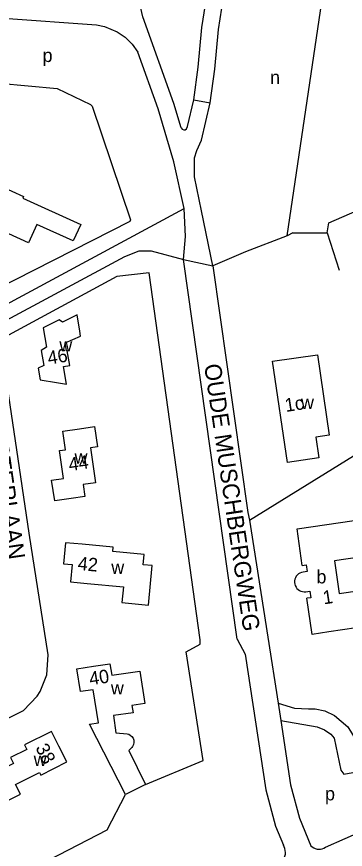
# Model space of a CAD drawing. Extents: x 162427 to 165104, y 384242 to 386287.
# Drawn here: x 164107.7 to 164205.6, y 384987.1 to 385235.6 of the extents above; entities that cross this region are included whole.
import ezdxf

# ---------------------------------------------------------------- set-up
doc = ezdxf.new("R2010")
doc.units = 0
for name, color, linetype in [('BLT_Basislijn', 7, 'Continuous'), ('BLT_Bebouwing', 7, 'Continuous'), ('BLT_Centroide', 7, 'Continuous'), ('BLT_Huisnummer', 7, 'Continuous'), ('BLT_Straatnaam', 7, 'Continuous'), ('BLT_Vlakafsluiter', 7, 'Continuous')]:
    doc.layers.add(name, color=color, linetype=linetype)

msp = doc.modelspace()

# ---------------------------------------------------------------- linework, layer by layer
at = {"layer": 'BLT_Basislijn'}
for p, q in [((164160.47, 385210.78), (164165.39, 385209.89)), ((164100.08, 385147.29), (164157.64, 385178.38)), ((164190.02, 385171.08), (164188.33, 385170.23)), ((164200.2, 385171.13), (164203.77, 385160)), ((164173.43, 385049.82), (164157.35, 385163.13)), ((164177.09, 385085.33), (164231.58, 385119.14)), ((164177.09, 385085.33), (164182.55, 385050.49)), ((164182.55, 385050.49), (164185.59, 385030.74)), ((164199.69, 384987.79), (164222.18, 384997.74))]:
    msp.add_line(p, q, dxfattribs=at)
for points in [[(164160.47, 385210.78), (164161.77, 385220.52), (164162.86, 385232.42), (164166.91, 385258.07), (164172.04, 385290.52), (164175.66, 385314.64)], [(164165.39, 385209.89), (164166.74, 385219.96), (164167.83, 385231.8), (164171.85, 385257.29), (164176.98, 385289.76), (164177.71, 385294.61)], [(164188.33, 385170.23), (164202.97, 385269.71), (164249.26, 385269.42), (164252.4, 385292.86)], [(163719.72, 385227.97), (163758.68, 385247.63), (163770.66, 385252.86), (163778.27, 385255.65), (163784.87, 385257.24), (163794.66, 385258.7), (163805.08, 385259.08), (163818.56, 385258.83), (163833.99, 385257.58), (163913.29, 385250.18), (164037.15, 385240.92), (164075.9, 385237.19), (164131.43, 385233.17)], [(163916.82, 385191.96), (163921.31, 385239.96), (164098.8, 385223.67), (164102.32, 385215.75), (164119.72, 385214.13), (164129.68, 385209.43), (164130.16, 385208.88), (164141.58, 385174.96), (164141.42, 385174.48), (164095.83, 385151.36)], [(164156.7, 385202.45), (164154.56, 385209.7), (164145.31, 385235.52), (164144.24, 385239.86)], [(164131.43, 385233.17), (164133.82, 385232.66), (164137.66, 385231.04), (164140.03, 385229.46), (164142.06, 385227.41), (164143.75, 385225.06)], [(164157.64, 385178.38), (164154.47, 385192.32), (164149.81, 385208.15), (164143.75, 385225.06)], [(164156.7, 385202.45), (164157.02, 385202.02), (164157.54, 385201.88), (164157.92, 385201.86), (164158.32, 385202.17), (164158.63, 385202.88), (164160.47, 385210.78)], [(164160.66, 385187.86), (164160.66, 385193.47), (164161.41, 385195.64), (164162.81, 385198.76), (164165.39, 385209.89)], [(164166.18, 385161.25), (164162.77, 385177.62), (164160.66, 385187.86)], [(164200.2, 385171.13), (164200.68, 385174.05), (164230.63, 385187.13)], [(164157.35, 385163.13), (164158.02, 385169.98), (164157.64, 385178.38)], [(164190.02, 385171.08), (164200.2, 385171.13)], [(164188.33, 385170.23), (164175.9, 385165.47), (164166.18, 385161.25)], [(164101.95, 385143.68), (164139.93, 385164.03), (164144.2, 385165.75), (164147.78, 385165.76), (164157.35, 385163.13)], [(164166.18, 385161.25), (164176.56, 385087.63), (164177.09, 385085.33)], [(164146.05, 385006.5), (164163.21, 385013.65), (164158.19, 385046.13), (164162.37, 385048.39), (164162.37, 385049.63), (164147.21, 385159.13), (164137.48, 385158.1), (164102.85, 385139.32)], [(163874.37, 384930.96), (163895.29, 384941.69), (163907.09, 384947.2), (163917.37, 384950.98), (163935.42, 384955.81), (163969.74, 384962.82), (163983.96, 384967.15), (163993.92, 384971.28), (164109.67, 385028.61), (164113.77, 385032.85), (164114.66, 385034.28), (164116.64, 385039.21), (164117.08, 385045.22), (164111.4, 385081.45), (164102.85, 385139.32)], [(164173.43, 385049.82), (164175.75, 385045.35), (164181.97, 385004.92), (164184.8, 384994.08), (164187.17, 384988.37)], [(164185.59, 385030.74), (164190.51, 385029.27), (164194.66, 385029.06)], [(164185.59, 385030.74), (164186.38, 385025.61)], [(164194.66, 385029.06), (164196.65, 385029.06), (164199.51, 385028.45), (164202.44, 385027.1), (164206.36, 385023.7), (164208.9, 385019.64), (164219.53, 385019.77), (164232.23, 385018.65)], [(164186.38, 385025.61), (164189.32, 385006.44), (164191.93, 384996.48), (164195.36, 384988.2)], [(164186.38, 385025.61), (164197.23, 385023.67), (164199.45, 385022.76), (164201.34, 385021.55), (164202.3, 385020.28), (164204.29, 385010.8), (164205.15, 385009.62), (164216.58, 385011.65)], [(163937.33, 384901.61), (163960, 384913.99), (163988.04, 384927.89), (163995.38, 384923.27), (164065.59, 384957.24), (164134.64, 384992.97), (164140.11, 385003.48)], [(164184.41, 384982.15), (164184.97, 384982.29), (164185.5, 384982.51), (164185.99, 384982.8), (164186.44, 384983.16), (164186.84, 384983.58), (164187.17, 384984.05), (164187.44, 384984.55), (164187.63, 384985.1), (164187.75, 384985.66), (164187.78, 384986.23), (164187.74, 384986.8), (164187.62, 384987.37), (164187.42, 384987.91), (164187.17, 384988.37)], [(164195.36, 384988.2), (164195.76, 384987.86), (164196.21, 384987.58), (164196.69, 384987.38), (164197.19, 384987.25), (164197.71, 384987.2), (164198.24, 384987.23), (164198.75, 384987.34), (164199.24, 384987.53), (164199.69, 384987.79)]]:
    msp.add_lwpolyline(points, dxfattribs=at)
at = {"layer": 'BLT_Bebouwing'}
for p, q in [((164141.09, 385016.66), (164146.05, 385006.5)), ((164146.05, 385006.5), (164140.11, 385003.48))]:
    msp.add_line(p, q, dxfattribs=at)
for points in [[(164102.76, 385185.15), (164109.75, 385181.99), (164109.49, 385181.41), (164126.78, 385173.58), (164124.56, 385168.68), (164113.65, 385173.62), (164111.17, 385168.17), (164105.36, 385170.8), (164102.99, 385171.88), (164101.34, 385168.24), (164093.59, 385171.75), (164095.65, 385176.31), (164098.12, 385181.77), (164100.7, 385180.6), (164102.76, 385185.15)], [(164126.49, 385141.75), (164125.66, 385146.68), (164121.3, 385144.46), (164120.32, 385145.17), (164115.61, 385142.8), (164116.58, 385136.98), (164114.99, 385136), (164115.73, 385131.55), (164114.04, 385130.74), (164114.64, 385127.21), (164119.57, 385126.41), (164122.48, 385125.94), (164121.6, 385131.2), (164123.5, 385131.52), (164122.77, 385135.88), (164122.55, 385135.97), (164122.17, 385138.25), (164126.73, 385140.31), (164126.49, 385141.75)], [(164126.36, 385112.67), (164130.86, 385113.34), (164131.75, 385107.29), (164129.66, 385106.98), (164131.2, 385096.51), (164127.51, 385095.97), (164128.03, 385092.46), (164123.95, 385091.86), (164119.01, 385091.13), (164118.1, 385097.28), (164121.65, 385097.81), (164120.43, 385106.12), (164122.24, 385106.39), (164121.42, 385111.94), (164126.36, 385112.67)], [(164192.73, 385071.88), (164191.23, 385082.74), (164212.34, 385085.85), (164213.95, 385074.96), (164202.38, 385073.26), (164203.83, 385063.48), (164215.39, 385065.18), (164216.97, 385054.44), (164200.71, 385052.03), (164195.76, 385051.3), (164194.17, 385062.08)], [(164128.68, 385066.46), (164139.49, 385065.45), (164139.06, 385060.78), (164146.95, 385060.05), (164148.05, 385071.83), (164145.42, 385072.07), (164145.71, 385075.17), (164136.36, 385076.05), (164136.48, 385077.32), (164127.18, 385078.18), (164122.2, 385078.65), (164121.61, 385072.35), (164124.18, 385072.11), (164123.7, 385066.92), (164128.68, 385066.46)], [(164192.73, 385071.88), (164193.96, 385072.01), (164194.22, 385070.04), (164193.02, 385069.87)], [(164193.02, 385069.87), (164192.55, 385069.76), (164192.1, 385069.57), (164191.69, 385069.32), (164191.32, 385069), (164191.02, 385068.62), (164190.77, 385068.2), (164190.61, 385067.74), (164190.52, 385067.26), (164190.5, 385066.78), (164190.57, 385066.3), (164190.71, 385065.83), (164190.93, 385065.4), (164191.22, 385065.01), (164191.57, 385064.67), (164191.97, 385064.39), (164192.41, 385064.18), (164192.87, 385064.05), (164193.36, 385063.99), (164193.84, 385064.02), (164193.89, 385064.02)], [(164193.89, 385064.02), (164195.08, 385064.19), (164195.37, 385062.2), (164194.17, 385062.08)], [(164140.11, 385003.48), (164129.36, 385024.45), (164132.02, 385024.85), (164130.52, 385034.78), (164126.68, 385034.2), (164125.65, 385041.04), (164130.59, 385041.79), (164135.49, 385042.53), (164136.01, 385039.08), (164144.38, 385040.35), (164145.85, 385030.68), (164142.04, 385030.1), (164142.37, 385027.93), (164136.49, 385027.04), (164137.26, 385021.92), (164140.65, 385021.59), (164141.09, 385021.47), (164141.55, 385021.23), (164142, 385020.84), (164142.37, 385020.31), (164142.59, 385019.68), (164142.62, 385019.03), (164142.49, 385018.42), (164142.2, 385017.85), (164141.96, 385017.56), (164141.09, 385016.66)], [(164120.29, 385017.9), (164118.02, 385022.36), (164110.02, 385018.29), (164110.69, 385016.98), (164105.83, 385014.51), (164106.72, 385012.76), (164100.91, 385009.8), (164103.17, 385005.35), (164105.04, 385001.68), (164108.84, 385003.61), (164107.36, 385006.51), (164114.45, 385010.11), (164114.87, 385009.29), (164122.65, 385013.25), (164120.29, 385017.9)]]:
    msp.add_lwpolyline(points, dxfattribs=at)
msp.add_lwpolyline([(164183.97, 385132.78), (164197.33, 385134.72), (164200.81, 385110.76), (164196.84, 385110.18), (164197.76, 385103.92), (164188.36, 385102.55)], close=True, dxfattribs=at)
at = {"layer": 'BLT_Vlakafsluiter'}
msp.add_line((164157.35, 385163.13), (164166.18, 385161.25), dxfattribs=at)

# ---------------------------------------------------------------- texts
at = {"layer": 'BLT_Centroide'}
for s, p in [('p', (164115.4, 385222.07)), ('n', (164183.19, 385215.51)), ('w', (164120.39, 385135.7)), ('w', (164192.41, 385118.53)), ('w', (164124.92, 385102.23)), ('w', (164135.87, 385069.34)), ('b', (164197.02, 385066.5)), ('w', (164135.75, 385033.36)), ('w', (164112.75, 385012.03)), ('p', (164199.58, 385001.76))]:
    msp.add_text(s, height=4, dxfattribs=at).set_placement(p)
at = {"layer": 'BLT_Huisnummer'}
for s, rotation, p in [('46', 9.5111, (164117.22, 385131.76)), ('1c', 8.7296, (164187.91, 385117.64)), ('44', 8.4015, (164123.43, 385099.98)), ('42', 354.6699, (164125.77, 385070.54)), ('1', 8.7296, (164199.23, 385060.23)), ('40', 8.6033, (164129.59, 385036.07)), ('38', 296.9392, (164113.18, 385017.48))]:
    msp.add_text(s, height=4, rotation=rotation, dxfattribs=at).set_placement(p)
at = {"layer": 'BLT_Straatnaam'}
for s, rotation, p in [('OUDE MUSCHBERGWEG', 278.4062, (164163.52, 385131.67)), ('MINISTERLAAN', 278.4124, (164098.09, 385122.24))]:
    msp.add_text(s, height=5, rotation=rotation, dxfattribs=at).set_placement(p)

doc.saveas('drawing.dxf')
